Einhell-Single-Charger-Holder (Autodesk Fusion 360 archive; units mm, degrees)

design "Einhell-Single-Charger-Holder" references "Base"
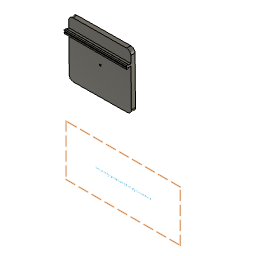
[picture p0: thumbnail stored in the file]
parameter "mount_screw_width" = 5.6
parameter "margin_to_chassis_outside" = 3.6
parameter "screw_padding_horizontal" = 20
parameter "screw_padding_vertical" = 50
parameter "mount_screw_stick_width" = 4.3
parameter "screw_thicker_width" = 3.4
component_insert "Component Insert"
sketch "Frenchfinity Top" plane through (0, 55.6118, 0) normal (0, 1, 0) x axis (-1, 0, 0)
  line L1 (0, 52.6059) -> (-59, 52.6059)
  line L2 (0, 60) -> (0, 52.6059)
  line L3 (-59, 60) -> (0, 60)
  line L4 (-59, 52.6059) -> (-59, 60)
  line L5 (-59, 60) -> (0, 60)
canvas "Canvas1"
sketch "Sketch2" plane through (0, 0, 0) normal (0, 1, 0) x axis (1, 0, 0)
  circle C1 centre (62.6119, -59.2024) radius 4.4325
  circle C2 centre (12.6238, -58.6768) radius 4.4325
  circle C3 centre (38.8576, 34.7582) radius 4.4325
  circle C4 centre (38.8576, 34.7582) radius 2.8
  circle C5 centre (62.6119, -59.2024) radius 2.8
  circle C6 centre (12.6238, -58.6768) radius 2.8
  concentric C3 C4
  concentric C1 C5
  concentric C2 C6
  dimension "d3" diameter C4 = 5.6 (= "mount_screw_width")
  dimension "d4" diameter C5 = 5.6 (= "mount_screw_width")
  dimension "d5" diameter C6 = 5.6 (= "mount_screw_width")
sketch "Sketch3" plane through (0, 55.6118, 0) normal (0, 1, 0) x axis (-1, 0, 0)
  line L1 (-12.6238, 58.6768) -> (-62.6119, 59.2024)
  line L2 (-13.609, -35.0237) -> (-12.6238, 58.6768)
  line L3 (-63.5971, -34.4981) -> (-13.609, -35.0237)
  line L4 (-62.6119, 59.2024) -> (-63.5971, -34.4981)
  line L5 (-83.8063, -54.2867) -> (6.1796, -55.2328)
  line L6 (-82.4006, 79.4116) -> (-83.8063, -54.2867)
  line L7 (7.5853, 78.4654) -> (-82.4006, 79.4116)
  line L8 (6.1796, -55.2328) -> (7.5853, 78.4654)
  line L9 (-114.12, -83.9697) -> (35.8626, -85.5466)
  line L10 (-112.0835, 109.7253) -> (-114.12, -83.9697)
  line L11 (37.8991, 108.1484) -> (-112.0835, 109.7253)
  line L12 (35.8626, -85.5466) -> (37.8991, 108.1484)
  line L13 (-112.3989, 79.727) -> (-82.4006, 79.4116)
  line L14 (37.5837, 78.15) -> (7.5853, 78.4654)
  line L15 (36.178, -55.5482) -> (6.1796, -55.2328)
  line L16 (-113.8046, -53.9713) -> (-83.8063, -54.2867)
  circle C1 centre (-62.6119, 59.2024) radius 2.8
  circle C2 centre (-12.6238, 58.6768) radius 2.8
  circle C3 centre (-38.8576, -34.7582) radius 2.8
  point P3 (-12.6238, 58.6768)
  point P6 (-12.6238, 58.6768)
  point P2 (-62.6119, 59.2024)
  point P5 (-62.6119, 59.2024)
  point P17 (-112.3989, 79.727)
  point P18 (37.5837, 78.15)
  point P19 (36.178, -55.5482)
  point P20 (-113.8046, -53.9713)
  perpendicular L1 L2
  parallel L1 L3
  parallel L2 L4
  coincident P3 P6
  coincident P2 P5
  coincident L10 P17
  perpendicular L10 L13
  coincident L12 P18
  perpendicular L12 L14
  coincident L12 P19
  perpendicular L12 L15
  coincident L10 P20
  perpendicular L10 L16
  dimension "d8" = -20 (= "screw_padding_horizontal * -1")
  dimension "d9" = -50 (= "screw_padding_vertical * -1")
extrude "Extrude1" new body sketch "Sketch3" profile of C1 C2 C3 L8 L7 L6 L5 L12 L10 L13 L14 L15 L16 along normal blind 10
sketch "Sketch4" plane through (0, 65.6118, 0) normal (0, 1, 0) x axis (-1, 0, 0)
  line L1 (36.178, -55.5482) -> (-113.8046, -53.9713)
  line L2 (37.5837, 78.15) -> (36.178, -55.5482)
  line L3 (-112.3989, 79.727) -> (37.5837, 78.15)
  line L4 (-113.8046, -53.9713) -> (-112.3989, 79.727)
  circle C1 centre (-62.6119, 59.2024) radius 2.15
  circle C2 centre (-12.6238, 58.6768) radius 2.15
  circle C3 centre (-38.8576, -34.7582) radius 2.15
  point P6 (-62.6119, 59.2024)
  point P9 (-62.6119, 59.2024)
  point P7 (-12.6238, 58.6768)
  point P10 (-12.6238, 58.6768)
  point P8 (-38.8576, -34.7582)
  point P11 (-38.8576, -34.7582)
  coincident P6 P9
  coincident P7 P10
  coincident P8 P11
  dimension "d13" diameter C1 = 4.3 (= "mount_screw_stick_width")
  dimension "d14" diameter C2 = 4.3 (= "mount_screw_stick_width")
  dimension "d15" diameter C3 = 4.3 (= "mount_screw_stick_width")
extrude "Extrude2" add sketch "Sketch4" profile of C1 C2 C3 along normal blind 3.6 (= "margin_to_chassis_outside")
sketch "Sketch6" plane through (0, 69.2118, 0) normal (0, 1, 0) x axis (-1, 0, 0)
  circle C1 centre (-62.6119, 59.2024) radius 2.15
  circle C2 centre (-62.6119, 59.2024) radius 2.8
  circle C3 centre (-12.6238, 58.6768) radius 2.8
  circle C4 centre (-38.8576, -34.7582) radius 2.8
extrude "Extrude3" new body sketch "Sketch6" along normal blind 3.4 (= "screw_thicker_width")
sketch "Sketch7" plane through (0, 55.6118, 0) normal (0, -1, 0) x axis (1, 0, 0)
  dimension "d29" = 3
fillet "Fillet1" radius 1
fillet "Fillet2" radius 10
extrude "Extrude4" add of existing geometry to an object
extrude "Extrude5" add of existing geometry to an object
extrude "Extrude6" cut sketch "Sketch7" against normal blind 2
sketch "Filename" plane through (0, 0, 0) normal (0, 1, 0) x axis (1, 0, 0)
  dimension "d32" = 5

design "Base"
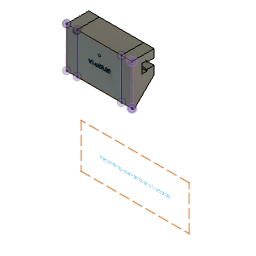
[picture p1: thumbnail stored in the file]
parameter "wall_anchor_height" = 60
parameter "wall_anchor_width" = 20
parameter "wall_anchor_angle" = 45
parameter "width_per_slot" = 40
parameter "slot_inner_width" = 8.5
parameter "slot_inner_height" = 4.5
parameter "slot_outer_width" = 5.6
parameter "slot_outer_height" = 6.5
parameter "slot_dept" = 15
parameter "print_tolerance" = 0.12
parameter "base_plate_thickness" = 16
parameter "base_plate_slot_height" = 50
parameter "wall_anchor_angle_rounded_border" = 1.5
parameter "base_plate_screw_hole_diameter" = 4
parameter "base_plate_screw_head_diameter" = 8
parameter "base_plate_screw_head_height" = 4
parameter "base_plate_screw_hole_side_distance" = 7
parameter "slot_screw_head_width" = 4.42 (= "4.3 mm + print_tolerance")
parameter "slot_screw_thread_width" = 2.12 (= "2 mm + print_tolerance")
parameter "slot_screw_head_height" = 2.12 (= "2 mm + print_tolerance")
parameter "width" = 59
parameter "filament_hole_width" = 1.7
sketch "Side" plane through (0, 0, 0) normal (1, 0, 0) x axis (0, 1, 0)
  line L1 (39.6118, 0) -> (19.6118, 0)
  line L2 (39.6118, 60) -> (39.6118, 0)
  line L3 (19.6118, 60) -> (39.6118, 60)
  line L4 (19.6118, 0) -> (19.6118, 60)
  line L5 (39.6118, 39.6118) -> (0, 0)
  line L6 (56.0196, 0) -> (0, 0)
  point P1 (0, 0)
  point P6 (0, 0)
  point P7 (39.6118, 39.6118)
  point P2 (19.6118, 0)
  point P3 (39.6118, 0)
  point P5 (19.6118, 60)
  horizontal L1
  vertical L2
  horizontal L3
  vertical L4
  horizontal L6
  coincident P1 P6
  coincident L2 P7
  dimension "d4" distance P2 P3 = 20 (= "wall_anchor_width")
  dimension "d5" distance P2 P5 = 60 (= "wall_anchor_height")
  dimension "d6" angle L5 L6 = 45 (= "wall_anchor_angle")
extrude "Extrude1" new body sketch "Side" profile of L1 L2 L3 L4 L5 along normal blind 40 (= "width_per_slot")
sketch "Slot LeftToRight" plane through (0, 0, 0) normal (-1, 0, 0) x axis (0, -1, 0)
  line L1 (-19.6118, 60) -> (-19.6118, 19.6118)
  line L2 (-39.6118, 60) -> (-19.6118, 60)
  line L3 (-39.6118, 39.6118) -> (-39.6118, 60)
  line L4 (-19.6118, 19.6118) -> (-39.6118, 39.6118)
  line L5 (-39.6118, 52.6059) -> (-39.6118, 49.8059)
  line L6 (-39.6118, 47.0059) -> (-39.6118, 49.8059)
  line L7 (-33.1118, 52.6059) -> (-39.6118, 52.6059)
  line L8 (-28.6118, 49.8059) -> (-39.6118, 49.8059)
  line L9 (-28.6118, 54.0559) -> (-28.6118, 49.8059)
  line L10 (-33.1118, 54.0559) -> (-28.6118, 54.0559)
  line L11 (-33.1118, 52.6059) -> (-33.1118, 54.0559)
  line L12 (-28.6118, 45.5559) -> (-28.6118, 49.8059)
  line L13 (-33.1118, 45.5559) -> (-28.6118, 45.5559)
  line L14 (-33.1118, 47.0059) -> (-33.1118, 45.5559)
  line L15 (-33.1118, 47.0059) -> (-39.6118, 47.0059)
  point P6 (-39.6118, 49.8059)
  point P7 (-39.6118, 52.6059)
  point P17 (-39.6118, 47.0059)
  point P9 (-33.1118, 52.6059)
  point P16 (-33.1118, 47.0059)
  point P10 (-28.6118, 49.8059)
  point P13 (-28.6118, 49.8059)
  point P11 (-28.6118, 54.0559)
  point P14 (-28.6118, 45.5559)
  point P12 (-33.1118, 54.0559)
  point P15 (-33.1118, 45.5559)
  midpoint L3 P6
  parallel L3 L5
  parallel L3 L6
  perpendicular L3 L7
  perpendicular L6 L8
  perpendicular L8 L9
  perpendicular L9 L10
  symmetric P7 L8 P17
  symmetric P9 L8 P16
  symmetric P10 L8 P13
  symmetric L8 P11 P14
  symmetric L8 P12 P15
  dimension "d80" distance P6 P7 = 2.8 (= "slot_outer_width / 2")
  dimension "d82" distance P7 P9 = 6.5 (= "slot_outer_height")
  dimension "d84" distance P6 P10 = 11 (= "slot_outer_height + slot_inner_height")
  dimension "d85" distance P10 P11 = 4.25 (= "slot_inner_width / 2")
  dimension "d86" distance P11 P12 = 4.5 (= "slot_inner_height")
extrude "Extrude3" cut sketch "Slot LeftToRight" profile of L3 L5 L6 L7 L9 L10 L11 L12 L13 L14 L15 against normal blind 40 (magnitude of "width_per_slot * -1")
sketch "Plate" plane through (0, 39.6118, 0) normal (0, 1, 0) x axis (-1, 0, 0)
  line L1 (0, 39.6118) -> (-40, 39.6118)
  line L2 (-40, 60) -> (0, 60)
  line L3 (0, 10) -> (0, 60)
  line L4 (-40, 10) -> (-40, 60)
  line L5 (-40, 10) -> (0, 10)
  line L6 (-40, 47.0059) -> (0, 47.0059)
  line L7 (-40, 52.6059) -> (-40, 60)
  line L8 (0, 60) -> (0, 52.6059)
  line L9 (0, 52.6059) -> (-40, 52.6059)
  line L10 (-40, 60) -> (0, 60)
  line L11 (-40, 39.6118) -> (-40, 47.0059)
  line L12 (0, 47.0059) -> (0, 39.6118)
  point P2 (0, 60)
  point P3 (-40, 60)
  point P4 (0, 10)
  point P5 (-40, 10)
  perpendicular L1 L3
  perpendicular L1 L4
  dimension "d36" distance P2 P3 = 40 (= "width_per_slot")
  dimension "d37" distance P2 P4 = 50 (= "base_plate_slot_height")
  dimension "d39" distance P3 P5 = 50 (= "base_plate_slot_height")
extrude "Extrude6" new body sketch "Plate" profile of L1 L2 L3 L4 L5 L6 L7 L8 L9 L10 along normal blind 16 (= "base_plate_thickness") bodies "Base plate with slot"
sketch "Slot" plane through (0, 0, 0) normal (-1, 0, 0) x axis (0, -1, 0)
  line L1 (-19.6118, 60) -> (-19.6118, 19.6118)
  line L2 (-39.6118, 60) -> (-19.6118, 60)
  line L3 (-39.6118, 52.6059) -> (-39.6118, 60)
  line L4 (-33.1118, 52.6059) -> (-39.6118, 52.6059)
  line L5 (-33.1118, 54.0559) -> (-33.1118, 52.6059)
  line L6 (-28.6118, 54.0559) -> (-33.1118, 54.0559)
  line L7 (-28.6118, 45.5559) -> (-28.6118, 54.0559)
  line L8 (-33.1118, 45.5559) -> (-28.6118, 45.5559)
  line L9 (-33.1118, 47.0059) -> (-33.1118, 45.5559)
  line L10 (-39.6118, 47.0059) -> (-33.1118, 47.0059)
  line L11 (-39.6118, 39.6118) -> (-39.6118, 47.0059)
  line L12 (-19.6118, 19.6118) -> (-39.6118, 39.6118)
  line L13 (-33.1118, 52.6059) -> (-39.6118, 52.6059)
  line L14 (-33.1118, 54.0559) -> (-33.1118, 52.6059)
  line L15 (-28.6118, 54.0559) -> (-33.1118, 54.0559)
  line L16 (-28.6118, 45.5559) -> (-28.6118, 54.0559)
  line L17 (-33.1118, 45.5559) -> (-28.6118, 45.5559)
  line L18 (-33.1118, 47.0059) -> (-33.1118, 45.5559)
  line L19 (-39.6118, 47.0059) -> (-33.1118, 47.0059)
  line L20 (-39.6118, 10) -> (-39.6118, 60)
  line L21 (-32.9918, 52.4859) -> (-39.6118, 52.4859)
  line L22 (-32.9918, 53.9359) -> (-32.9918, 52.4859)
  line L23 (-28.7318, 53.9359) -> (-32.9918, 53.9359)
  line L24 (-28.7318, 45.6759) -> (-28.7318, 53.9359)
  line L25 (-32.9918, 45.6759) -> (-28.7318, 45.6759)
  line L26 (-32.9918, 47.1259) -> (-32.9918, 45.6759)
  line L27 (-39.6118, 47.1259) -> (-32.9918, 47.1259)
  line L28 (-33.1118, 52.6059) -> (-39.6118, 52.6059)
  line L29 (-33.1118, 52.6059) -> (-33.1118, 54.0559)
  line L30 (-28.6118, 54.0559) -> (-33.1118, 54.0559)
  line L31 (-28.6118, 45.5559) -> (-28.6118, 54.0559)
  line L32 (-33.1118, 45.5559) -> (-28.6118, 45.5559)
  line L33 (-33.1118, 47.0059) -> (-33.1118, 45.5559)
  line L34 (-39.6118, 47.0059) -> (-33.1118, 47.0059)
  line L35 (-39.6118, 47.0059) -> (-39.6118, 52.6059)
  line L36 (-49.1118, 52.6059) -> (-55.6118, 52.6059)
  line L37 (-49.1118, 52.6059) -> (-49.1118, 54.0559)
  line L38 (-44.6118, 54.0559) -> (-49.1118, 54.0559)
  line L39 (-44.6118, 45.5559) -> (-44.6118, 54.0559)
  line L40 (-49.1118, 45.5559) -> (-44.6118, 45.5559)
  line L41 (-49.1118, 47.0059) -> (-49.1118, 45.5559)
  line L42 (-55.6118, 47.0059) -> (-49.1118, 47.0059)
  line L43 (-55.6118, 47.0059) -> (-55.6118, 52.6059)
  point P15 (-39.6118, 52.6059)
  point P33 (-39.6118, 52.6059)
  point P16 (-33.1118, 52.6059)
  point P34 (-33.1118, 52.6059)
  point P17 (-33.1118, 54.0559)
  point P35 (-33.1118, 54.0559)
  point P36 (-33.1118, 52.6059)
  point P18 (-28.6118, 54.0559)
  point P37 (-28.6118, 54.0559)
  point P19 (-28.6118, 45.5559)
  point P38 (-28.6118, 45.5559)
  point P10 (-28.6118, 45.5559)
  point P39 (-28.6118, 45.5559)
  point P11 (-33.1118, 45.5559)
  point P40 (-33.1118, 45.5559)
  point P41 (-33.1118, 45.5559)
  point P12 (-33.1118, 47.0059)
  point P42 (-33.1118, 47.0059)
  point P21 (-33.1118, 47.0059)
  point P43 (-33.1118, 47.0059)
  point P22 (-39.6118, 47.0059)
  point P44 (-39.6118, 47.0059)
  point P45 (-39.6118, 52.6059)
  point P46 (-39.6118, 47.0059)
  coincident P15 P33
  coincident P16 P34
  coincident P17 P35
  coincident P16 P36
  coincident P18 P37
  coincident P19 P38
  coincident P10 P39
  coincident P11 P40
  coincident P11 P41
  coincident P12 P42
  coincident P21 P43
  coincident P22 P44
  coincident P15 P45
  coincident P22 P46
  dimension "d91" = 0.12 (= "print_tolerance")
  dimension "d96" R-Pattern1-uDistance = -16 (= "base_plate_thickness * -1")
  dimension "d97" R-Pattern1-vDistance = 0
extrude "Extrude7" add sketch "Slot" profile of L20 L24 L23 L27 L22 L25 L26 L21 against normal blind 40 (magnitude of "width_per_slot * -1")
extrude "Extrude8" cut sketch "Slot" profile of L36 L37 L38 L39 L40 L41 L42 L43 no distance stored
sketch "Sketch3" plane through (0, 0, 0) normal (-1, 0, 0) x axis (0, -1, 0)
  line L1 (-32.9918, 47.1259) -> (-39.6118, 47.1259)
  line L2 (-32.9918, 45.6759) -> (-32.9918, 47.1259)
  line L3 (-28.7318, 45.6759) -> (-32.9918, 45.6759)
  line L4 (-28.7318, 53.9359) -> (-28.7318, 45.6759)
  line L5 (-32.9918, 53.9359) -> (-28.7318, 53.9359)
  line L6 (-32.9918, 52.4859) -> (-32.9918, 53.9359)
  line L7 (-39.6118, 52.4859) -> (-32.9918, 52.4859)
  line L8 (-44.6118, 45.5559) -> (-44.6118, 54.0559)
  line L9 (-32.9918, 52.4859) -> (-39.6118, 52.4859)
  line L10 (-32.9918, 53.9359) -> (-32.9918, 52.4859)
  line L11 (-28.7318, 53.9359) -> (-32.9918, 53.9359)
  line L12 (-28.7318, 45.6759) -> (-28.7318, 53.9359)
  line L13 (-32.9918, 45.6759) -> (-28.7318, 45.6759)
  line L14 (-32.9918, 47.1259) -> (-32.9918, 45.6759)
  line L15 (-39.6118, 47.1259) -> (-32.9918, 47.1259)
  line L16 (-39.6118, 47.1259) -> (-39.6118, 52.4859)
  line L17 (-55.6118, 52.4859) -> (-48.9918, 52.4859)
  line L18 (-48.9918, 52.4859) -> (-48.9918, 53.9359)
  line L19 (-48.9918, 53.9359) -> (-44.7318, 53.9359)
  line L20 (-44.7318, 45.6759) -> (-44.7318, 53.9359)
  line L21 (-48.9918, 45.6759) -> (-44.7318, 45.6759)
  line L22 (-48.9918, 47.1259) -> (-48.9918, 45.6759)
  line L23 (-55.6118, 47.1259) -> (-48.9918, 47.1259)
  line L24 (-55.6118, 47.1259) -> (-55.6118, 52.4859)
  line L25 (-55.6118, 47.0059) -> (-49.1118, 47.0059)
  line L26 (-55.6118, 10) -> (-55.6118, 47.0059)
  line L27 (-39.6118, 10) -> (-55.6118, 10)
  line L28 (-39.6118, 47.1259) -> (-39.6118, 10)
  line L29 (-39.6118, 60) -> (-39.6118, 52.4859)
  line L30 (-55.6118, 60) -> (-39.6118, 60)
  line L31 (-55.6118, 52.6059) -> (-55.6118, 60)
  line L32 (-49.1118, 52.6059) -> (-55.6118, 52.6059)
  line L33 (-49.1118, 54.0559) -> (-49.1118, 52.6059)
  line L34 (-44.6118, 54.0559) -> (-49.1118, 54.0559)
  line L35 (-49.1118, 45.5559) -> (-44.6118, 45.5559)
  line L36 (-49.1118, 47.0059) -> (-49.1118, 45.5559)
  point P9 (-39.6118, 52.4859)
  point P20 (-39.6118, 52.4859)
  point P19 (-39.6118, 47.1259)
  point P21 (-39.6118, 47.1259)
  coincident P9 P20
  coincident P19 P21
  dimension "d105" R-Pattern1-vDistance = 0
extrude "Extrude3" new body sketch "Sketch3" profile of L17 L18 L19 L20 L21 L22 L23 L24 against normal blind 40 (magnitude of "width_per_slot * -1")
sketch "Screw hole" plane through (0, 28.6118, 0) normal (0, 1, 0) x axis (-1, 0, 0)
  line L1 (0, 54.0559) -> (0, 45.5559)
  line L2 (-40, 54.0559) -> (0, 54.0559)
  line L3 (-40, 45.5559) -> (-40, 54.0559)
  line L4 (0, 45.5559) -> (-40, 45.5559)
  line L5 (0, 45.5559) -> (-40, 54.0559)
  line L6 (-40, 45.5559) -> (0, 54.0559)
  circle C1 centre (-20, 49.8059) radius 2.21
  circle C2 centre (-20, 49.8059) radius 1.06
  point P4 (-40, 54.0559)
  point P6 (-40, 54.0559)
  point P2 (0, 45.5559)
  point P7 (0, 45.5559)
  point P3 (0, 54.0559)
  point P8 (0, 54.0559)
  point P5 (-40, 45.5559)
  point P9 (-40, 45.5559)
  point P10 (-20, 49.8059)
  coincident P4 P6
  coincident P2 P7
  coincident P3 P8
  coincident P5 P9
  midpoint L5 P10
  concentric C1 C2
  dimension "d119" diameter C1 = 4.42 (= "slot_screw_head_width")
  dimension "d120" diameter C2 = 2.12 (= "slot_screw_thread_width")
extrude "Extrude4" cut sketch "Screw hole" profile of C2 against normal blind 2000
extrude "Extrude5" cut sketch "Screw hole" profile of C1 C2 no distance stored
fillet "Fillet1" radius 1.5 (= "wall_anchor_angle_rounded_border")
work_plane "WorkPlane1" sketch "Slot LeftToRight" AlongDistance -20 (= "-width_per_slot / 2")
sketch "Screw head" plane through (20, 0, 0) normal (-1, 0, 0) x axis (0, -1, 0)
  line L1 (-28.6118, 52.0159) -> (-28.6118, 47.5959)
  line L2 (-26.4918, 52.0159) -> (-26.4918, 47.5959)
  line L3 (-26.4918, 48.7459) -> (-26.4918, 50.8659)
  line L4 (-26.4918, 50.8659) -> (-28.6118, 52.0159)
  line L5 (-26.4918, 52.0159) -> (-28.6118, 52.0159)
  point P3 (-28.6118, 52.0159)
  point P8 (-28.6118, 52.0159)
  point P6 (-26.4918, 50.8659)
  point P9 (-26.4918, 50.8659)
  point P10 (-28.6118, 52.0159)
  point P5 (-26.4918, 52.0159)
  point P11 (-26.4918, 52.0159)
  coincident P3 P8
  coincident P6 P9
  coincident P3 P10
  coincident P5 P11
revolve "Revolve1" sketch "Screw head" AlongAngle 360
sketch "Plate" plane through (0, 39.6118, 0) normal (0, 1, 0) x axis (-1, 0, 0)
  line L1 (0, 39.6118) -> (-40, 39.6118)
  line L2 (-40, 60) -> (0, 60)
  line L3 (0, 10) -> (0, 60)
  line L4 (-40, 10) -> (-40, 60)
  line L5 (-40, 10) -> (0, 10)
  line L6 (-40, 47.0059) -> (0, 47.0059)
  line L7 (-40, 39.6118) -> (-40, 47.0059)
  line L8 (0, 47.0059) -> (0, 39.6118)
  line L9 (0, 52.6059) -> (-40, 52.6059)
  line L10 (-40, 60) -> (0, 60)
  line L11 (0, 60) -> (0, 52.6059)
  line L12 (-40, 52.6059) -> (-40, 60)
  point P2 (0, 60)
  point P3 (-40, 60)
  point P4 (0, 10)
  point P5 (-40, 10)
  perpendicular L1 L3
  perpendicular L1 L4
  dimension "d36_1" distance P2 P3 = 40 (= "width_per_slot")
  dimension "d37_1" distance P2 P4 = 50 (= "base_plate_slot_height")
  dimension "d39_1" distance P3 P5 = 50 (= "base_plate_slot_height")
extrude "Extrude6" new body sketch "Plate" profile of L1 L2 L3 L4 L5 L6 L7 L8 L9 L10 along normal blind 16 (= "base_plate_thickness") named "d89_1" bodies "Base plate with slot"
sketch "Slot" plane through (0, 0, 0) normal (-1, 0, 0) x axis (0, -1, 0)
  line L1 (-19.6118, 60) -> (-19.6118, 23.2332)
  line L2 (-39.6118, 60) -> (-19.6118, 60)
  line L3 (-39.6118, 52.6059) -> (-39.6118, 60)
  line L4 (-33.1118, 52.6059) -> (-39.6118, 52.6059)
  line L5 (-33.1118, 54.0559) -> (-33.1118, 52.6059)
  line L6 (-28.6118, 54.0559) -> (-33.1118, 54.0559)
  line L7 (-28.6118, 45.5559) -> (-28.6118, 54.0559)
  line L8 (-33.1118, 45.5559) -> (-28.6118, 45.5559)
  line L9 (-33.1118, 47.0059) -> (-33.1118, 45.5559)
  line L10 (-39.6118, 47.0059) -> (-33.1118, 47.0059)
  line L11 (-39.6118, 39.6118) -> (-39.6118, 47.0059)
  line L12 (-22.1725, 22.1725) -> (-39.6118, 39.6118)
  line L13 (-33.1118, 52.6059) -> (-39.6118, 52.6059)
  line L14 (-33.1118, 54.0559) -> (-33.1118, 52.6059)
  line L15 (-28.6118, 54.0559) -> (-33.1118, 54.0559)
  line L16 (-28.6118, 45.5559) -> (-28.6118, 54.0559)
  line L17 (-33.1118, 45.5559) -> (-28.6118, 45.5559)
  line L18 (-33.1118, 47.0059) -> (-33.1118, 45.5559)
  line L19 (-39.6118, 47.0059) -> (-33.1118, 47.0059)
  line L20 (-39.6118, 10) -> (-39.6118, 60)
  line L21 (-32.9918, 52.4859) -> (-39.6118, 52.4859)
  line L22 (-32.9918, 53.9359) -> (-32.9918, 52.4859)
  line L23 (-28.7318, 53.9359) -> (-32.9918, 53.9359)
  line L24 (-28.7318, 45.6759) -> (-28.7318, 53.9359)
  line L25 (-32.9918, 45.6759) -> (-28.7318, 45.6759)
  line L26 (-32.9918, 47.1259) -> (-32.9918, 45.6759)
  line L27 (-39.6118, 47.1259) -> (-32.9918, 47.1259)
  line L28 (-33.1118, 52.6059) -> (-39.6118, 52.6059)
  line L29 (-33.1118, 52.6059) -> (-33.1118, 54.0559)
  line L30 (-28.6118, 54.0559) -> (-33.1118, 54.0559)
  line L31 (-28.6118, 45.5559) -> (-28.6118, 54.0559)
  line L32 (-33.1118, 45.5559) -> (-28.6118, 45.5559)
  line L33 (-33.1118, 47.0059) -> (-33.1118, 45.5559)
  line L34 (-39.6118, 47.0059) -> (-33.1118, 47.0059)
  line L35 (-39.6118, 47.0059) -> (-39.6118, 52.6059)
  line L36 (-49.1118, 52.6059) -> (-55.6118, 52.6059)
  line L37 (-49.1118, 52.6059) -> (-49.1118, 54.0559)
  line L38 (-44.6118, 54.0559) -> (-49.1118, 54.0559)
  line L39 (-44.6118, 45.5559) -> (-44.6118, 54.0559)
  line L40 (-49.1118, 45.5559) -> (-44.6118, 45.5559)
  line L41 (-49.1118, 47.0059) -> (-49.1118, 45.5559)
  line L42 (-55.6118, 47.0059) -> (-49.1118, 47.0059)
  line L43 (-55.6118, 47.0059) -> (-55.6118, 52.6059)
  arc A1 centre (-21.1118, 23.2332) radius 1.5 clockwise from (-19.6118, 23.2332) to (-22.1725, 22.1725)
  point P15 (-39.6118, 52.6059)
  point P33 (-39.6118, 52.6059)
  point P16 (-33.1118, 52.6059)
  point P34 (-33.1118, 52.6059)
  point P17 (-33.1118, 54.0559)
  point P35 (-33.1118, 54.0559)
  point P36 (-33.1118, 52.6059)
  point P18 (-28.6118, 54.0559)
  point P37 (-28.6118, 54.0559)
  point P19 (-28.6118, 45.5559)
  point P38 (-28.6118, 45.5559)
  point P10 (-28.6118, 45.5559)
  point P39 (-28.6118, 45.5559)
  point P11 (-33.1118, 45.5559)
  point P40 (-33.1118, 45.5559)
  point P41 (-33.1118, 45.5559)
  point P12 (-33.1118, 47.0059)
  point P42 (-33.1118, 47.0059)
  point P21 (-33.1118, 47.0059)
  point P43 (-33.1118, 47.0059)
  point P22 (-39.6118, 47.0059)
  point P44 (-39.6118, 47.0059)
  point P45 (-39.6118, 52.6059)
  point P46 (-39.6118, 47.0059)
  coincident P15 P33
  coincident P16 P34
  coincident P17 P35
  coincident P16 P36
  coincident P18 P37
  coincident P19 P38
  coincident P10 P39
  coincident P11 P40
  coincident P11 P41
  coincident P12 P42
  coincident P21 P43
  coincident P22 P44
  coincident P15 P45
  coincident P22 P46
  dimension "d91_1" = 0.12 (= "print_tolerance")
  dimension "d96_1" R-Pattern1-uDistance = -16 (= "base_plate_thickness * -1")
  dimension "d97_1" R-Pattern1-vDistance = 0
extrude "Extrude8" cut sketch "Slot" profile of L36 L37 L38 L39 L40 L41 L42 L43 no distance stored
sketch "Screw" plane through (0, 55.6118, 0) normal (0, 1, 0) x axis (-1, 0, 0)
  line L1 (-40, 47.0059) -> (0, 47.0059)
  line L2 (-40, 10) -> (-40, 47.0059)
  line L3 (0, 10) -> (-40, 10)
  line L4 (0, 47.0059) -> (0, 10)
  line L5 (-33, 17) -> (-33, 40.0059)
  line L6 (-7, 17) -> (-33, 17)
  line L7 (-7, 40.0059) -> (-7, 17)
  line L8 (-33, 40.0059) -> (-7, 40.0059)
  circle C1 centre (-33, 17) radius 4
  circle C2 centre (-33, 17) radius 2
  point P7 (-33, 17)
  point P10 (-33, 17)
  coincident P7 P10
  concentric C1 C2
  dimension "d127" = -7 (= "base_plate_screw_hole_side_distance * -1")
  dimension "d128" diameter C1 = 8
  dimension "d129" diameter C2 = 4
rectangular_pattern "R-Pattern2" countU 1 (= "floor(( width / mm ) / ( width_per_slot / cm * 10 ))") uSpaceDistance 40 (= "width_per_slot") vSpaceDistance 0
work_plane "WorkPlane2"
extrude "Extrude12" new body of existing geometry no distance stored
mirror "Mirror3" mirrorStitchTolerance 0.1
sketch "filename" plane through (0, 19.6118, 0) normal (0, -1, 0) x axis (1, 0, 0)
  dimension "d216" = 3
sketch "Sketch14" plane through (0, 19.6118, 0) normal (0, -1, 0) x axis (1, 0, 0)
  line L1 (49.5, 60) -> (49.5, 23.2332)
  line L2 (40, 23.2332) -> (40, 60)
  line L3 (49.5, 23.2332) -> (40, 23.2332)
  line L4 (49.5, 60) -> (49.5, 23.2332)
  line L5 (40, 60) -> (49.5, 60)
  line L6 (0, 60) -> (0, 23.2332)
  line L7 (-9.5, 60) -> (0, 60)
  line L8 (-9.5, 23.2332) -> (-9.5, 60)
  line L9 (0, 23.2332) -> (-9.5, 23.2332)
  curve K1
  curve K2
  curve K3
  curve K4
  point P4 (49.5, 23.2332)
  point P2 (-9.5, 60)
  coincident P4
  coincident P2
  dimension "d229" Text1-Height = 3
extrude "Extrude19" cut sketch "Sketch14" against normal blind 2
extrude "Extrude14" cut of existing geometry blind 9.5 (= "( width_per_slot - width ) / -2")
extrude "Extrude15" cut of existing geometry blind 9.5 (= "( width_per_slot - width ) / -2")
extrude "Extrude9" cut of existing geometry blind -39 (= "-width_per_slot + 1 mm")
extrude "Extrude10" add of existing geometry blind 58 (= "width - 1 mm")
sketch "Sketch7" plane through (0, 39.6118, 0) normal (0, -1, 0) x axis (1, 0, 0)
  dimension "d236" = 3
extrude "Extrude11" cut sketch "Sketch7" against normal blind 2
sketch "File name" plane through (0, 39.6118, 0) normal (0, -1, 0) x axis (1, 0, 0)
  line L1 (23.5624, 30.0752) -> (23.325, 30.0752)
  line L2 (23.5624, 27.063) -> (23.5624, 30.0752)
  line L3 (23.1941, 27.063) -> (23.5624, 27.063)
  line L4 (23.1941, 29.4102) -> (23.1941, 27.063)
  curve K1 (22.8441, 29.1564) -> (23.1941, 29.4102)
  curve K2 (22.4574, 28.9661) -> (22.8441, 29.1564)
  line L5 (22.4574, 29.3222) -> (22.4574, 28.9661)
  curve K3 (22.9976, 29.6741) -> (22.4574, 29.3222)
  curve K4 (23.325, 30.0752) -> (22.9976, 29.6741)
  line L6 (26.7896, 27.063) -> (27.2295, 28.7349)
  line L7 (26.4048, 27.063) -> (26.7896, 27.063)
  line L8 (25.7398, 29.2362) -> (26.4048, 27.063)
  line L9 (26.1204, 29.2362) -> (25.7398, 29.2362)
  line L10 (26.4662, 27.9818) -> (26.1204, 29.2362)
  line L11 (26.5952, 27.5152) -> (26.4662, 27.9818)
  curve K5 (26.7077, 27.9634) -> (26.5952, 27.5152)
  line L12 (27.0535, 29.2362) -> (26.7077, 27.9634)
  line L13 (27.4321, 29.2362) -> (27.0535, 29.2362)
  line L14 (27.7575, 27.9756) -> (27.4321, 29.2362)
  line L15 (27.866, 27.5602) -> (27.7575, 27.9756)
  line L16 (27.9908, 27.9797) -> (27.866, 27.5602)
  line L17 (28.3632, 29.2362) -> (27.9908, 27.9797)
  line L18 (28.7213, 29.2362) -> (28.3632, 29.2362)
  line L19 (28.0419, 27.063) -> (28.7213, 29.2362)
  line L20 (27.6593, 27.063) -> (28.0419, 27.063)
  line L21 (27.3134, 28.3645) -> (27.6593, 27.063)
  line L22 (27.2295, 28.7349) -> (27.3134, 28.3645)
  line L23 (25.5965, 27.9634) -> (25.5965, 28.3338)
  line L24 (24.4649, 27.9634) -> (25.5965, 27.9634)
  line L25 (24.4649, 28.3338) -> (24.4649, 27.9634)
  line L26 (25.5965, 28.3338) -> (24.4649, 28.3338)
  line L27 (21.1293, 27.063) -> (21.9519, 29.2362)
  line L28 (20.7855, 27.063) -> (21.1293, 27.063)
  line L29 (19.9587, 29.2362) -> (20.7855, 27.063)
  line L30 (20.3475, 29.2362) -> (19.9587, 29.2362)
  line L31 (20.8141, 27.9347) -> (20.3475, 29.2362)
  curve K6 (20.9533, 27.4968) -> (20.8141, 27.9347)
  curve K7 (21.0904, 27.9102) -> (20.9533, 27.4968)
  line L32 (21.5733, 29.2362) -> (21.0904, 27.9102)
  line L33 (21.9519, 29.2362) -> (21.5733, 29.2362)
  line L34 (0, 47.1259) -> (59, 47.1259)
  line L35 (0, 10) -> (0, 47.1259)
  line L36 (59, 10) -> (0, 10)
  line L37 (59, 47.1259) -> (59, 10)
  curve K8
  curve K9
  curve K10
  curve K11
  curve K12 (29.984, 29.052) -> (29.4171, 28.8638)
  curve K13 (30.9171, 28.08) -> (30.647, 28.7799)
  curve K14 (30.6797, 27.3761) -> (30.9171, 28.08)
  line L38 (29.3148, 27.8815) -> (28.928, 27.8488)
  curve K15 (32.5604, 28.1885) -> (32.8632, 28.475)
  curve K16 (30.647, 28.7799) -> (29.984, 29.052)
  curve K17 (32.7343, 27.1898) -> (33.1068, 27.7076)
  line L39 (29.4171, 28.8638) -> (29.5788, 29.6701)
  curve K18 (29.8919, 27.0118) -> (30.6797, 27.3761)
  curve K19 (29.2227, 27.241) -> (29.8919, 27.0118)
  curve K20 (28.928, 27.8488) -> (29.2227, 27.241)
  curve K21 (32.8632, 28.475) -> (32.8653, 28.4013)
  line L40 (28.9935, 28.4811) -> (29.3394, 28.4361)
  line L41 (29.2841, 30.022) -> (28.9935, 28.4811)
  curve K22 (29.5133, 27.4559) -> (29.3148, 27.8815)
  curve K23 (29.8919, 27.3147) -> (29.5133, 27.4559)
  curve K24 (30.3421, 27.5152) -> (29.8919, 27.3147)
  curve K25 (30.5263, 28.0473) -> (30.3421, 27.5152)
  curve K26 (30.3482, 28.5445) -> (30.5263, 28.0473)
  curve K27 (29.8857, 28.7267) -> (30.3482, 28.5445)
  curve K28 (29.5645, 28.6448) -> (29.8857, 28.7267)
  curve K29 (29.3394, 28.4361) -> (29.5645, 28.6448)
  line L42 (30.7759, 30.022) -> (29.2841, 30.022)
  line L43 (30.7759, 29.6701) -> (30.7759, 30.022)
  line L44 (29.5788, 29.6701) -> (30.7759, 29.6701)
  curve K30 (35.7323, 30.0752) -> (35.1879, 29.8992)
  curve K31 (36.1559, 29.977) -> (35.7323, 30.0752)
  curve K32 (35.1879, 29.8992) -> (34.8626, 29.3979)
  line L45 (31.6681, 27.7894) -> (31.3141, 27.7567)
  curve K33 (32.4621, 27.3924) -> (32.1654, 27.3147)
  curve K34 (32.6729, 27.5991) -> (32.4621, 27.3924)
  curve K35 (32.81, 27.9511) -> (32.6729, 27.5991)
  curve K36 (33.1047, 29.4675) -> (32.7364, 29.9177)
  curve K37 (33.2316, 28.6243) -> (33.1047, 29.4675)
  curve K38 (33.1068, 27.7076) -> (33.2316, 28.6243)
  curve K39 (32.147, 28.08) -> (32.5604, 28.1885)
  curve K40 (36.2766, 27.1878) -> (36.602, 27.6892)
  curve K41 (35.7323, 27.0118) -> (36.2766, 27.1878)
  curve K42 (36.4567, 29.6967) -> (36.1559, 29.977)
  curve K43 (36.6429, 29.2505) -> (36.4567, 29.6967)
  curve K44 (36.7104, 28.5425) -> (36.6429, 29.2505)
  curve K45 (36.602, 27.6892) -> (36.7104, 28.5425)
  curve K46 (32.1572, 27.0118) -> (32.7343, 27.1898)
  curve K47 (31.5822, 27.2062) -> (32.1572, 27.0118)
  curve K48 (31.3141, 27.7567) -> (31.5822, 27.2062)
  curve K49 (34.7541, 28.5425) -> (35.0508, 27.3228)
  curve K50 (35.0508, 27.3228) -> (35.7323, 27.0118)
  curve K51 (37.3816, 27.3228) -> (38.0631, 27.0118)
  curve K52 (37.0849, 28.5425) -> (37.3816, 27.3228)
  curve K53 (37.1934, 29.3979) -> (37.0849, 28.5425)
  curve K54 (37.5188, 29.8992) -> (37.1934, 29.3979)
  curve K55 (38.0631, 30.0752) -> (37.5188, 29.8992)
  curve K56 (38.4867, 29.977) -> (38.0631, 30.0752)
  curve K57 (38.7875, 29.6967) -> (38.4867, 29.977)
  curve K58 (38.9737, 29.2505) -> (38.7875, 29.6967)
  curve K59 (39.0413, 28.5425) -> (38.9737, 29.2505)
  curve K60 (38.9328, 27.6892) -> (39.0413, 28.5425)
  curve K61 (38.6074, 27.1878) -> (38.9328, 27.6892)
  curve K62 (38.0631, 27.0118) -> (38.6074, 27.1878)
  curve K63 (31.84, 27.4272) -> (31.6681, 27.7894)
  curve K64 (32.1654, 27.3147) -> (31.84, 27.4272)
  curve K65 (32.8653, 28.4013) -> (32.81, 27.9511)
  curve K66 (31.5167, 28.3501) -> (32.147, 28.08)
  curve K67 (31.2589, 29.0623) -> (31.5167, 28.3501)
  curve K68 (31.5269, 29.7969) -> (31.2589, 29.0623)
  curve K69 (32.2022, 30.0752) -> (31.5269, 29.7969)
  curve K70 (32.7364, 29.9177) -> (32.2022, 30.0752)
  curve K71 (34.8626, 29.3979) -> (34.7541, 28.5425)
  line L46 (34.2159, 27.063) -> (34.2159, 27.4825)
  line L47 (33.7964, 27.063) -> (34.2159, 27.063)
  line L48 (33.7964, 27.4825) -> (33.7964, 27.063)
  line L49 (34.2159, 27.4825) -> (33.7964, 27.4825)
  dimension "d239" Text1-Height = 3
sketch "Sketch4" plane through (40, 0, 0) normal (1, 0, 0) x axis (0, 1, 0)
  line L1 (44.7318, 53.9359) -> (48.9918, 53.9359)
  line L2 (44.7318, 45.6759) -> (44.7318, 53.9359)
  line L3 (48.9918, 45.6759) -> (44.7318, 45.6759)
  line L4 (48.9918, 47.1259) -> (48.9918, 45.6759)
  line L5 (55.6118, 47.1259) -> (48.9918, 47.1259)
  line L6 (55.6118, 52.4859) -> (55.6118, 47.1259)
  line L7 (48.9918, 52.4859) -> (55.6118, 52.4859)
  line L8 (48.9918, 53.9359) -> (48.9918, 52.4859)
  circle C1 centre (44.7318, 49.8059) radius 0.85
  point P10 (44.7318, 49.8059)
  midpoint L2 P10
  dimension "d241" diameter C1 = 1.7 (= "filament_hole_width")
extrude "Extrude4" cut sketch "Sketch4" profile of L2 C1 no distance stored
sketch "Sketch15" plane through (-9.5, 0, 0) normal (-1, 0, 0) x axis (0, -1, 0)
  line L1 (-19.6118, 60) -> (-19.6118, 23.2332)
  line L2 (-39.6118, 60) -> (-19.6118, 60)
  line L3 (-39.6118, 52.6059) -> (-39.6118, 60)
  line L4 (-33.1118, 52.6059) -> (-39.6118, 52.6059)
  line L5 (-33.1118, 54.0559) -> (-33.1118, 52.6059)
  line L6 (-28.6118, 54.0559) -> (-33.1118, 54.0559)
  line L7 (-28.6118, 45.5559) -> (-28.6118, 54.0559)
  line L8 (-33.1118, 45.5559) -> (-28.6118, 45.5559)
  line L9 (-33.1118, 47.0059) -> (-33.1118, 45.5559)
  line L10 (-39.6118, 47.0059) -> (-33.1118, 47.0059)
  line L11 (-39.6118, 39.6118) -> (-39.6118, 47.0059)
  line L12 (-22.1725, 22.1725) -> (-39.6118, 39.6118)
  arc A1 centre (-21.1118, 23.2332) radius 1.5 clockwise from (-19.6118, 23.2332) to (-22.1725, 22.1725)
  circle C1 centre (-28.6118, 49.8059) radius 0.85
  point P16 (-28.6118, 49.8059)
  midpoint L7 P16
  dimension "d244" diameter C1 = 1.7 (= "filament_hole_width")
sketch "Sketch9" plane through (59, 0, 0) normal (1, 0, 0) x axis (0, 1, 0)
  line L1 (49.1118, 47.0059) -> (55.6118, 47.0059)
  line L2 (49.1118, 45.5559) -> (49.1118, 47.0059)
  line L3 (44.6118, 45.5559) -> (49.1118, 45.5559)
  line L4 (44.6118, 54.0559) -> (44.6118, 45.5559)
  line L5 (49.1118, 54.0559) -> (44.6118, 54.0559)
  line L6 (49.1118, 52.6059) -> (49.1118, 54.0559)
  line L7 (55.6118, 52.6059) -> (49.1118, 52.6059)
  line L8 (55.6118, 60) -> (55.6118, 52.6059)
  line L9 (39.6118, 60) -> (55.6118, 60)
  line L10 (39.6118, 52.4859) -> (39.6118, 60)
  line L11 (32.9918, 52.4859) -> (39.6118, 52.4859)
  line L12 (32.9918, 53.9359) -> (32.9918, 52.4859)
  line L13 (28.7318, 53.9359) -> (32.9918, 53.9359)
  line L14 (28.7318, 45.6759) -> (28.7318, 53.9359)
  line L15 (32.9918, 45.6759) -> (28.7318, 45.6759)
  line L16 (32.9918, 47.1259) -> (32.9918, 45.6759)
  line L17 (39.6118, 47.1259) -> (32.9918, 47.1259)
  line L18 (39.6118, 10) -> (39.6118, 47.1259)
  line L19 (55.6118, 10) -> (39.6118, 10)
  line L20 (55.6118, 47.0059) -> (55.6118, 10)
  circle C1 centre (28.7318, 49.8059) radius 0.85
  circle C2 centre (44.6118, 49.8059) radius 0.85
  point P22 (28.7318, 49.8059)
  point P23 (44.6118, 49.8059)
  midpoint L14 P22
  midpoint L4 P23
  dimension "d247" diameter C1 = 1.7 (= "filament_hole_width")
  dimension "d250" diameter C2 = 1.7 (= "filament_hole_width")
extrude "Extrude12" cut sketch "Sketch9" profile of L4 L14 C1 C2 no distance stored
sketch "Sketch16" plane through (0, 19.6118, 0) normal (0, -1, 0) x axis (1, 0, 0)
  dimension "d253" = 3
extrude "Extrude22" cut sketch "Sketch16" against normal blind 2
extrude "Extrude23" cut sketch "Sketch15" profile of L7 C1 against normal blind 2000
sketch "Sketch17" plane through (0, 19.6118, 0) normal (0, -1, 0) x axis (1, 0, 0)
  line L1 (0, 60) -> (40, 60)
  line L2 (40, 23.2332) -> (0, 23.2332)
  curve K1
  curve K2
  curve K3
  curve K4
  line L3 (40, 60) -> (40, 23.2332)
  line L4 (0, 23.2332) -> (0, 60)
  line L5 (11.6431, 40.0635) -> (12.45, 42.2427)
  line L6 (11.2993, 40.061) -> (11.6431, 40.0635)
  line L7 (10.4569, 42.2283) -> (11.2993, 40.061)
  line L8 (10.8457, 42.2311) -> (10.4569, 42.2283)
  line L9 (11.3216, 40.933) -> (10.8457, 42.2311)
  curve K5 (11.4639, 40.4961) -> (11.3216, 40.933)
  curve K6 (11.5981, 40.9104) -> (11.4639, 40.4961)
  line L10 (12.0714, 42.2399) -> (11.5981, 40.9104)
  line L11 (12.45, 42.2427) -> (12.0714, 42.2399)
  line L12 (16.1037, 40.9962) -> (16.101, 41.3666)
  line L13 (14.9721, 40.988) -> (16.1037, 40.9962)
  line L14 (14.9694, 41.3584) -> (14.9721, 40.988)
  line L15 (16.101, 41.3666) -> (14.9694, 41.3584)
  curve K7 (23.0657, 41.2716) -> (23.3665, 41.5602)
  line L16 (19.8225, 40.9412) -> (19.4359, 40.9056)
  curve K8 (20.4832, 42.1165) -> (19.9177, 41.9241)
  curve K9 (21.4233, 41.1512) -> (21.1481, 41.8491)
  curve K10 (21.191, 40.4456) -> (21.4233, 41.1512)
  line L17 (17.3032, 40.1044) -> (17.7311, 41.7794)
  line L18 (16.9185, 40.1016) -> (17.3032, 40.1044)
  line L19 (16.2377, 42.27) -> (16.9185, 40.1016)
  line L20 (16.6184, 42.2728) -> (16.2377, 42.27)
  line L21 (16.9733, 41.0209) -> (16.6184, 42.2728)
  line L22 (17.1055, 40.5552) -> (16.9733, 41.0209)
  curve K11 (17.2149, 41.0042) -> (17.1055, 40.5552)
  line L23 (17.5515, 42.2795) -> (17.2149, 41.0042)
  line L24 (17.9301, 42.2822) -> (17.5515, 42.2795)
  line L25 (18.2645, 41.024) -> (17.9301, 42.2822)
  line L26 (18.376, 40.6094) -> (18.2645, 41.024)
  line L27 (18.4978, 41.0298) -> (18.376, 40.6094)
  line L28 (18.8611, 42.289) -> (18.4978, 41.0298)
  line L29 (19.2192, 42.2915) -> (18.8611, 42.289)
  line L30 (18.5556, 40.1134) -> (19.2192, 42.2915)
  line L31 (18.1729, 40.1107) -> (18.5556, 40.1134)
  line L32 (17.8177, 41.4096) -> (18.1729, 40.1107)
  line L33 (17.7311, 41.7794) -> (17.8177, 41.4096)
  line L34 (14.0544, 43.0933) -> (13.817, 43.0916)
  line L35 (14.0761, 40.0811) -> (14.0544, 43.0933)
  line L36 (13.7078, 40.0784) -> (14.0761, 40.0811)
  line L37 (13.6909, 42.4256) -> (13.7078, 40.0784)
  curve K12 (13.3428, 42.1693) -> (13.6909, 42.4256)
  curve K13 (12.9574, 41.9762) -> (13.3428, 42.1693)
  line L38 (12.9548, 42.3323) -> (12.9574, 41.9762)
  curve K14 (13.4925, 42.6881) -> (12.9548, 42.3323)
  curve K15 (13.817, 43.0916) -> (13.4925, 42.6881)
  curve K16 (21.1481, 41.8491) -> (20.4832, 42.1165)
  curve K17 (23.2469, 40.2742) -> (23.6156, 40.7946)
  line L39 (19.9177, 41.9241) -> (20.0735, 42.7316)
  curve K18 (20.4058, 40.0756) -> (21.191, 40.4456)
  curve K19 (19.735, 40.3) -> (20.4058, 40.0756)
  curve K20 (19.4359, 40.9056) -> (19.735, 40.3)
  curve K21 (23.3665, 41.5602) -> (23.3691, 41.4866)
  line L40 (19.4969, 41.5384) -> (19.843, 41.4959)
  line L41 (19.7763, 43.0814) -> (19.4969, 41.5384)
  curve K22 (20.024, 40.517) -> (19.8225, 40.9412)
  curve K23 (20.4036, 40.3785) -> (20.024, 40.517)
  curve K24 (20.8524, 40.5823) -> (20.4036, 40.3785)
  curve K25 (21.0327, 41.1157) -> (20.8524, 40.5823)
  curve K26 (20.8511, 41.6116) -> (21.0327, 41.1157)
  curve K27 (20.3873, 41.7904) -> (20.8511, 41.6116)
  curve K28 (20.0666, 41.7062) -> (20.3873, 41.7904)
  curve K29 (19.843, 41.4959) -> (20.0666, 41.7062)
  line L42 (21.2681, 43.0922) -> (19.7763, 43.0814)
  line L43 (21.2706, 42.7402) -> (21.2681, 43.0922)
  line L44 (20.0735, 42.7316) -> (21.2706, 42.7402)
  curve K30 (26.2239, 43.1812) -> (25.6809, 43.0013)
  curve K31 (26.6482, 43.086) -> (26.2239, 43.1812)
  curve K32 (25.6809, 43.0013) -> (25.3591, 42.4976)
  line L45 (22.1764, 40.8661) -> (21.8226, 40.8308)
  curve K33 (22.9733, 40.4748) -> (22.6771, 40.3949)
  curve K34 (23.1825, 40.683) -> (22.9733, 40.4748)
  curve K35 (23.3171, 41.036) -> (23.1825, 40.683)
  curve K36 (23.6008, 42.5544) -> (23.2292, 43.002)
  curve K37 (23.7338, 41.7123) -> (23.6008, 42.5544)
  curve K38 (23.6156, 40.7946) -> (23.7338, 41.7123)
  curve K39 (22.6532, 41.1601) -> (23.0657, 41.2716)
  curve K40 (26.7891, 40.2977) -> (27.1108, 40.8014)
  curve K41 (26.246, 40.1178) -> (26.7891, 40.2977)
  curve K42 (26.9511, 42.8078) -> (26.6482, 43.086)
  curve K43 (27.1405, 42.3631) -> (26.9511, 42.8078)
  curve K44 (27.2131, 41.6555) -> (27.1405, 42.3631)
  curve K45 (27.1108, 40.8014) -> (27.2131, 41.6555)
  curve K46 (22.6711, 40.092) -> (23.2469, 40.2742)
  curve K47 (22.0947, 40.2822) -> (22.6711, 40.092)
  curve K48 (21.8226, 40.8308) -> (22.0947, 40.2822)
  curve K49 (25.2568, 41.6414) -> (25.5624, 40.4239)
  curve K50 (25.5624, 40.4239) -> (26.246, 40.1178)
  curve K51 (27.8931, 40.4408) -> (28.5768, 40.1346)
  curve K52 (27.5876, 41.6582) -> (27.8931, 40.4408)
  curve K53 (27.6899, 42.5144) -> (27.5876, 41.6582)
  curve K54 (28.0116, 43.0181) -> (27.6899, 42.5144)
  curve K55 (28.5547, 43.198) -> (28.0116, 43.0181)
  curve K56 (28.979, 43.1028) -> (28.5547, 43.198)
  curve K57 (29.2818, 42.8247) -> (28.979, 43.1028)
  curve K58 (29.4713, 42.3799) -> (29.2818, 42.8247)
  curve K59 (29.5439, 41.6724) -> (29.4713, 42.3799)
  curve K60 (29.4416, 40.8183) -> (29.5439, 41.6724)
  curve K61 (29.1199, 40.3146) -> (29.4416, 40.8183)
  curve K62 (28.5768, 40.1346) -> (29.1199, 40.3146)
  curve K63 (22.3509, 40.5051) -> (22.1764, 40.8661)
  curve K64 (22.6771, 40.3949) -> (22.3509, 40.5051)
  curve K65 (23.3691, 41.4866) -> (23.3171, 41.036)
  curve K66 (22.0209, 41.4257) -> (22.6532, 41.1601)
  curve K67 (21.758, 42.1359) -> (22.0209, 41.4257)
  curve K68 (22.0207, 42.8725) -> (21.758, 42.1359)
  curve K69 (22.694, 43.1557) -> (22.0207, 42.8725)
  curve K70 (23.2292, 43.002) -> (22.694, 43.1557)
  curve K71 (25.3591, 42.4976) -> (25.2568, 41.6414)
  line L46 (24.7293, 40.158) -> (24.7263, 40.5775)
  line L47 (24.3098, 40.155) -> (24.7293, 40.158)
  line L48 (24.3068, 40.5745) -> (24.3098, 40.155)
  line L49 (24.7263, 40.5775) -> (24.3068, 40.5745)
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  point P2 (40, 23.2332)
  point P4 (0, 60)
  coincident P2
  coincident P4
  dimension "d258" Text1-Height = 3
extrude "Extrude24" cut sketch "Sketch17" against normal blind 2
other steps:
create_component "CreateComponent1"
create_component "CreateComponent2"
create_component "CreateComponent3"
create_component "CreateComponent4"
named bodies: "Wall anchor part", "Base plate with slot"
